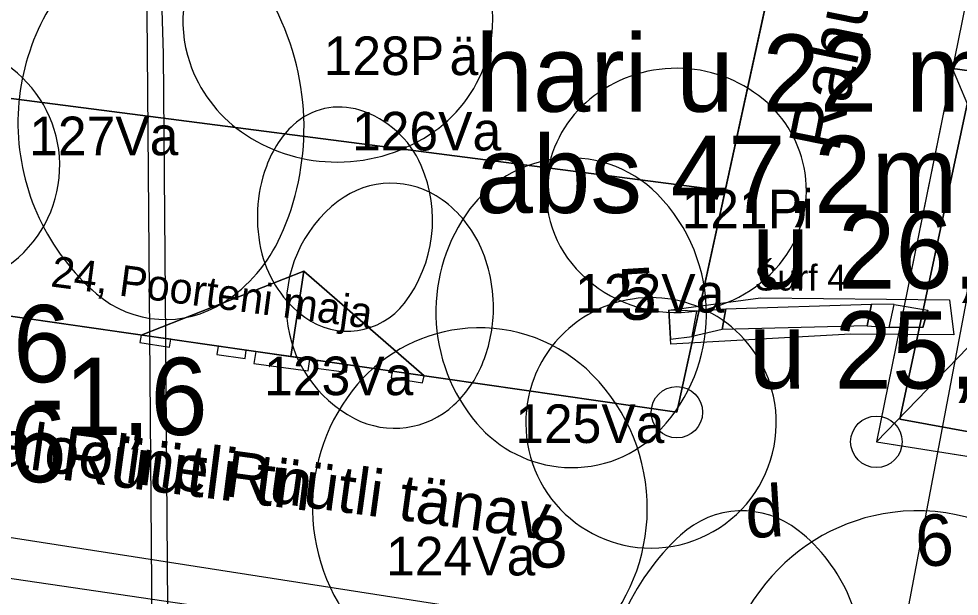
# Model space of a CAD drawing. Extents: x 738423 to 738903, y 6589762 to 6590172.
# Drawn here: x 738661.32 to 738697.88, y 6589853.54 to 6589875.99 of the extents above; entities that cross this region are included whole.
import ezdxf

# ---------------------------------------------------------------- set-up
doc = ezdxf.new("R2010")
doc.units = 0
for name, color, linetype in [('_1927_hoonestus', 7, 'Continuous'), ('_1927_katuse_kalded', 7, 'Continuous'), ('_1927_koordin_punktid_nr', 7, 'Continuous'), ('_1927_krundi_piir', 7, 'Continuous'), ('_a_ajalooline_maapind', 7, 'Continuous'), ('_a_olol_maapind', 7, 'Continuous'), ('_ajalooline_aadress', 7, 'Continuous'), ('_arheol_Raamatukogu_tekst', 7, 'Continuous'), ('_arheol_Suur10c_kõnnitee_plaadid', 7, 'Continuous'), ('_arheol_Suur10c_müür', 7, 'Continuous'), ('_arheol_Suur10c_sõidutee', 7, 'Continuous'), ('_arheol_Suur10c_tranžee', 7, 'Continuous'), ('a_dendro_II_Vkl_puu', 7, 'Continuous'), ('a_dendro_III_vk_puu', 7, 'Continuous'), ('a_dendro_puu_nr', 7, 'Continuous'), ('Default', 7, 'Continuous'), ('plan_ala', 7, 'Continuous'), ('v_olol_kitsendus_tehnov', 7, 'Continuous'), ('v_olol_kivimuur', 7, 'Continuous'), ('v_vormistus_tekst', 7, 'Continuous')]:
    doc.layers.add(name, color=color, linetype=linetype)

# ---------------------------------------------------------------- blocks, each defined once
blk = doc.blocks.new('_U564')
at = {"layer": 'Default'}
for centre, radius, start, end in [((0.00025099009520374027, -0.005055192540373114), 0.019094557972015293, 94.1124972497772, 134.51702665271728), ((0.0002459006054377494, -0.004984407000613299), 0.019023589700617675, 55.35000678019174, 94.11249724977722), ((0.002413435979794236, -0.0018482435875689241), 0.015211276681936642, 11.781229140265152, 55.3500067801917), ((-0.002483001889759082, -0.002274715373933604), 0.015195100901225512, 134.51702665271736, 180.0676771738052), ((0.0028111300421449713, -0.001765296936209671), 0.014805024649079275, 320.3120464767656, 11.781229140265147), ((-0.0028404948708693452, -0.002275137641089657), 0.014837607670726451, 180.06767717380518, 230.5602074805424), ((-0.00028961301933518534, 0.0008078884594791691), 0.018834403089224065, 275.0288867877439, 320.31204647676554), ((-0.0002910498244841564, 0.0008242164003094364), 0.01885079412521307, 230.56020748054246, 275.0288867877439)]:
    blk.add_arc(centre, radius, start, end, dxfattribs=at)
blk = doc.blocks.new('_U565')
at = {"layer": 'Default'}
for centre, radius, start, end in [((6.291324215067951e-05, -0.0048100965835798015), 0.02003728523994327, 93.63802698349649, 141.620131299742), ((1.0755175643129e-05, -0.003989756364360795), 0.019215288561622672, 47.2373133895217, 93.63802698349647), ((0.008279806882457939, 0.0049516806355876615), 0.007036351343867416, 326.00160298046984, 47.23731338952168), ((-0.010029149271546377, 0.003183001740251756), 0.0071633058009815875, 141.620131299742, 227.31101855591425), ((0.0031639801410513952, 0.008402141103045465), 0.013207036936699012, 297.16095567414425, 326.0016029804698), ((-0.005414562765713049, 0.00818571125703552), 0.01396929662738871, 227.31101855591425, 255.72135989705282), ((-0.0024036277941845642, 0.01925371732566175), 0.025403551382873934, 276.47252031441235, 297.16095567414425), ((-0.0024634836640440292, 0.019781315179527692), 0.025934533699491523, 255.72135989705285, 276.47252031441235)]:
    blk.add_arc(centre, radius, start, end, dxfattribs=at)
blk = doc.blocks.new('_U571')
at = {"layer": 'Default'}
for centre, radius, start, end in [((-0.001470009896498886, 0.001014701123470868), 0.00901042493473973, 85.84989655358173, 139.9854481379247), ((-0.0014878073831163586, 0.0007694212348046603), 0.009256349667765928, 43.48308981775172, 85.84989655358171), ((-0.000269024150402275, 6.4345285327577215e-06), 0.01057853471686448, 139.98544813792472, 189.65024392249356), ((-0.002518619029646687, -0.00020820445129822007), 0.0106770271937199, 4.160899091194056, 43.48308981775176), ((-0.0024551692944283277, -0.00020358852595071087), 0.01061340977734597, 325.0458822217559, 4.160899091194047), ((-0.00037917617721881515, -1.2295665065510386e-05), 0.01046680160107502, 189.65024392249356, 234.37896630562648), ((-0.0012850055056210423, -0.0010215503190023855), 0.009185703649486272, 282.866559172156, 325.0458822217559), ((-0.0012408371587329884, -0.0012149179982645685), 0.00898735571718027, 234.37896630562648, 282.866559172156)]:
    blk.add_arc(centre, radius, start, end, dxfattribs=at)
blk = doc.blocks.new('_U572')
at = {"layer": 'Default'}
for centre, radius, start, end in [((0.0006055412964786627, -0.0042978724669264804), 0.013370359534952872, 95.78793518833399, 134.72163124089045), ((0.0006103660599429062, -0.0043454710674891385), 0.013418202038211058, 57.679315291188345, 95.78793518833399), ((0.0025199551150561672, -0.0013272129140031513), 0.009846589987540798, 12.875543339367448, 57.67931529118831), ((-0.0019332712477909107, -0.0017342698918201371), 0.009762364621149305, 134.72163124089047, 180.63224075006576), ((0.0028947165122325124, -0.0012415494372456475), 0.009462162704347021, 318.8770820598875, 12.87554333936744), ((-0.002241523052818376, -0.0017376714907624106), 0.009454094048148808, 180.63224075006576, 231.2174139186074), ((4.354030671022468e-05, 0.0012476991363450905), 0.013247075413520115, 273.7532980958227, 318.87708205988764), ((5.212560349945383e-05, 0.001116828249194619), 0.013115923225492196, 231.21741391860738, 273.7532980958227)]:
    blk.add_arc(centre, radius, start, end, dxfattribs=at)
blk = doc.blocks.new('_U573')
at = {"layer": 'Default'}
for centre, radius, start, end in [((0.0006832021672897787, 0.002328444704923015), 0.009807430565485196, 99.69352009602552, 156.90409293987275), ((0.0007565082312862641, 0.0018992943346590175), 0.010242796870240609, 41.6418055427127, 99.69352009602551), ((0.0033334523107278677, 0.00419057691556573), 0.006794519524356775, 328.51143624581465, 41.6418055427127), ((-0.002092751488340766, 0.0035122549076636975), 0.006789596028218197, 156.90409293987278, 227.1622359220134), ((0.0013890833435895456, 0.005381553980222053), 0.009074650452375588, 297.72957352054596, 328.51143624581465), ((-0.0006159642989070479, 0.005104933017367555), 0.00896158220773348, 227.16223592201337, 250.19895822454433), ((0.00016828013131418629, 0.007703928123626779), 0.01169834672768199, 270.6931788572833, 297.72957352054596), ((0.0001732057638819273, 0.007296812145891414), 0.011291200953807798, 250.19895822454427, 270.6931788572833)]:
    blk.add_arc(centre, radius, start, end, dxfattribs=at)
blk = doc.blocks.new('_U574')
at = {"layer": 'Default'}
for centre, radius, start, end in [((-0.0019608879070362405, -0.0016410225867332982), 0.009734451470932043, 82.36591619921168, 131.76985429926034), ((-0.0019610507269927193, -0.0016422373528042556), 0.009735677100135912, 47.60610430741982, 82.36591619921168), ((-0.0019574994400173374, -0.0016448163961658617), 0.009739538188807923, 131.76985429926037, 181.1600261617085), ((-0.001964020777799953, -0.0016454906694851), 0.009740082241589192, 12.854403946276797, 47.60610430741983), ((-0.001964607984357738, -0.0016456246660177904), 0.009740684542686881, 329.7776812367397, 12.854403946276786), ((-0.001956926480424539, -0.0016448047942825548), 0.009740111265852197, 181.1600261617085, 233.9170109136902), ((-0.001960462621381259, -0.0016480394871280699), 0.009735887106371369, 286.68981658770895, 329.7776812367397), ((-0.0019601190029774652, -0.0016491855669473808), 0.009734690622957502, 233.91701091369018, 286.68981658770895)]:
    blk.add_arc(centre, radius, start, end, dxfattribs=at)
blk = doc.blocks.new('_U575')
at = {"layer": 'Default'}
for centre, radius, start, end in [((0.00042731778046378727, -0.002692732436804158), 0.01475472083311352, 95.42702457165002, 137.71551286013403), ((0.0004293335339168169, -0.002713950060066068), 0.01477603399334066, 53.94693546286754, 95.42702457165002), ((0.0017917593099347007, -0.0008423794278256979), 0.012461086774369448, 8.58220218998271, 53.946935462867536), ((-0.0012999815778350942, -0.0011218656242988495), 0.012419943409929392, 137.71551286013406, 184.01840102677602), ((0.0019030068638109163, -0.0008255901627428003), 0.012348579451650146, 318.9383698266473, 8.58220218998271), ((-0.0013715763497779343, -0.001126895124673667), 0.012348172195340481, 184.01840102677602, 230.9331406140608), ((9.492108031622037e-05, 0.0007495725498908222), 0.014746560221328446, 273.7559687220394, 318.9383698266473), ((9.916099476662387e-05, 0.0006849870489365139), 0.014681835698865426, 230.93314061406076, 273.7559687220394)]:
    blk.add_arc(centre, radius, start, end, dxfattribs=at)
blk = doc.blocks.new('_U578')
at = {"layer": 'Default'}
for centre, radius, start, end in [((0.0031046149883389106, 0.0007126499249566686), 0.010083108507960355, 58.964104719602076, 112.89361314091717), ((0.003381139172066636, 5.782187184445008e-05), 0.010793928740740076, 112.89361314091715, 149.17299112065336), ((0.0018851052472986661, -0.001314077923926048), 0.01244844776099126, 10.793615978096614, 58.964104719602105), ((0.005224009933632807, -0.001041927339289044), 0.012939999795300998, 149.1729911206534, 182.21275775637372), ((0.0016087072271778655, -0.0013667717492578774), 0.012729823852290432, 316.8121326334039, 10.793615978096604), ((0.005405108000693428, -0.0010349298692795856), 0.013121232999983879, 182.2127577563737, 217.26007191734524), ((0.0036931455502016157, -0.0023372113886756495), 0.010970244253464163, 217.26007191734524, 255.71243530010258), ((0.0034904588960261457, -0.0031331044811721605), 0.010148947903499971, 255.71243530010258, 316.8121326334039)]:
    blk.add_arc(centre, radius, start, end, dxfattribs=at)
blk = doc.blocks.new('_U576')
at = {"layer": 'Default'}
for centre, radius, start, end in [((-0.003355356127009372, -0.008989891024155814), 0.011452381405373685, 74.0956447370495, 108.61486101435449), ((-0.004187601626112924, -0.006519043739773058), 0.008845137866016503, 108.61486101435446, 148.07755350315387), ((-0.0027526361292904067, -0.006874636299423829), 0.009252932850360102, 61.394012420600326, 74.09564473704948), ((-0.001780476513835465, -0.005092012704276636), 0.007222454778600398, 47.00906118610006, 61.394012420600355), ((-0.00046350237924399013, -0.0036792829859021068), 0.005291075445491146, 346.8046159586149, 47.00906118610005), ((-0.0069482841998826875, -0.004799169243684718), 0.005592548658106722, 148.0775535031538, 236.8517004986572), ((-0.0028699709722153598, -0.0031150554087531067), 0.007762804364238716, 297.88330635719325, 346.80461595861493), ((-0.004202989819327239, -0.0005956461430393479), 0.010613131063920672, 236.85170049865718, 297.88330635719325)]:
    blk.add_arc(centre, radius, start, end, dxfattribs=at)
blk = doc.blocks.new('_U577')
at = {"layer": 'Default'}
for centre, radius, start, end in [((0.0003539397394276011, -0.0024772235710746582), 0.01753301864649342, 95.06339460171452, 143.64928581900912), ((0.0003509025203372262, -0.0024429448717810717), 0.017498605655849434, 47.6139328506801, 95.06339460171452), ((0.006587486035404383, 0.004390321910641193), 0.008247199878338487, 335.85757945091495, 47.613932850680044), ((-0.007106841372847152, 0.0030134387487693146), 0.008269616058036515, 143.6492858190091, 217.25092224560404), ((0.00326511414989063, 0.0058794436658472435), 0.011888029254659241, 301.16151048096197, 335.85757945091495), ((-0.004085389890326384, 0.00531108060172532), 0.012065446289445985, 217.2509222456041, 249.96613917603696), ((-0.0012283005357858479, 0.013310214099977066), 0.02057175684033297, 274.9595126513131, 301.16151048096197), ((-0.0012168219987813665, 0.01317793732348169), 0.020438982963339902, 249.96613917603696, 274.9595126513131)]:
    blk.add_arc(centre, radius, start, end, dxfattribs=at)
blk = doc.blocks.new('_U579')
at = {"layer": 'Default'}
for centre, radius, start, end in [((-0.00040469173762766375, -0.0036338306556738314), 0.00964728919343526, 90.6698769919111, 129.9961164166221), ((-0.00040544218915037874, -0.003569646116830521), 0.009583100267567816, 57.797497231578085, 90.6698769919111), ((-8.07417360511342e-05, -0.003054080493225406), 0.008973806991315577, 23.79468007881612, 57.797497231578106), ((-0.0008287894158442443, -0.0031283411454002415), 0.00898745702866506, 129.99611641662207, 170.80227761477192), ((0.00012402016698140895, -0.00296379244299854), 0.008750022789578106, 330.06495980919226, 23.79468007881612), ((-0.0010439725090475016, -0.0030934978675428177), 0.008769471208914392, 170.80227761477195, 225.9110289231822), ((-0.000504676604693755, -0.002601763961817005), 0.009475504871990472, 278.59055247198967, 330.06495980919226), ((-0.0005131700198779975, -0.002545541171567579), 0.009532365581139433, 225.91102892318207, 278.59055247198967)]:
    blk.add_arc(centre, radius, start, end, dxfattribs=at)

msp = doc.modelspace()

# ---------------------------------------------------------------- linework, layer by layer
at = {"layer": '_1927_hoonestus'}
for points in [[(738686.9079452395, 6589860.693508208), (738690.3471033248, 6589876.437885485), (738655.8073303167, 6589881.431195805), (738653.971798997, 6589865.440014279)], [(738697.6203724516, 6589874.0571487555), (738694.6643747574, 6589859.543029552), (738701.5400623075, 6589858.454941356), (738701.6672655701, 6589859.306230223), (738695.5732603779, 6589860.420766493), (738698.2877155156, 6589873.09433022), (738708.37858821, 6589871.7342214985), (738707.9133168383, 6589868.775731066), (738709.1198007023, 6589868.597835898), (738709.3011963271, 6589869.828059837), (738709.6806366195, 6589872.401421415)], [(738698.2877155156, 6589873.09433022), (738695.5732603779, 6589860.420766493), (738701.6672655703, 6589859.306230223), (738703.186385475, 6589869.472713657), (738707.9133168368, 6589868.775731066), (738708.37858821, 6589871.7342214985)], [(738666.0829986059, 6589863.6946406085), (738666.0226137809, 6589863.40871552), (738667.1852757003, 6589863.227095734), (738667.2336050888, 6589863.528823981)], [(738669.0718007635, 6589863.263917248), (738669.0201426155, 6589862.940511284), (738670.1198644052, 6589862.787255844), (738670.1682470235, 6589863.105905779)], [(738670.5345586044, 6589863.053115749), (738670.4615629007, 6589862.583018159), (738672.5748457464, 6589862.303206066), (738672.6434326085, 6589862.74920092)], [(738672.9281124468, 6589862.708175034), (738672.8870732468, 6589862.4073190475), (738674.0567893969, 6589862.247760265), (738674.0969044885, 6589862.539737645)], [(738675.8365255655, 6589862.289036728), (738675.7958205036, 6589862.024044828), (738677.0225699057, 6589861.835605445), (738677.0811269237, 6589862.109674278)]]:
    msp.add_lwpolyline(points, close=True, dxfattribs=at)
at = {"layer": '_1927_katuse_kalded'}
for points in [[(738654.1081769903, 6589873.783129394), (738655.0056644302, 6589881.575610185), (738655.8073303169, 6589881.431195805), (738690.3471033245, 6589876.437885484), (738688.7887442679, 6589869.303757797)], [(738694.6643747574, 6589859.543029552), (738701.0004892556, 6589866.068740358), (738697.6203724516, 6589874.0571487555)], [(738702.6437962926, 6589865.841516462), (738701.0004892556, 6589866.068740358), (738697.6203724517, 6589874.0571487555), (738709.6806366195, 6589872.401421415), (738709.1215019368, 6589868.609373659), (738707.9133168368, 6589868.775731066), (738703.1863854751, 6589869.472713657)], [(738654.1081769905, 6589873.783129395), (738688.788744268, 6589869.303757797), (738686.9079452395, 6589860.693508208), (738677.0811269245, 6589862.109674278), (738672.4076793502, 6589866.177638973), (738666.0829986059, 6589863.694640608), (738653.1607330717, 6589865.55689891)], [(738672.4076793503, 6589866.177638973), (738671.9013747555, 6589862.856140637), (738666.0829986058, 6589863.6946406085)], [(738672.4076793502, 6589866.177638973), (738677.0811269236, 6589862.109674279), (738671.9013747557, 6589862.856140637)], [(738694.6643747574, 6589859.543029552), (738701.5400623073, 6589858.454941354), (738702.6437962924, 6589865.841516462), (738701.0004892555, 6589866.0687403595)]]:
    msp.add_lwpolyline(points, close=True, dxfattribs=at)
at = {"layer": '_1927_koordin_punktid_nr'}
for centre in [(738686.9079452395, 6589860.693508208), (738694.6643747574, 6589859.543029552)]:
    msp.add_circle(centre, 0.9999999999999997, dxfattribs=at)
at = {"layer": '_1927_krundi_piir'}
for points in [[(738699.2597677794, 6589917.23983417), (738686.9079452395, 6589860.693508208), (738653.160733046, 6589865.556898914), (738635.0048101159, 6589867.503013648), (738638.1290908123, 6589898.927727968), (738639.279366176, 6589910.5516114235)], [(738701.0341576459, 6589890.819030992), (738694.6643747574, 6589859.543029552), (738727.0653921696, 6589854.415518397)]]:
    msp.add_lwpolyline(points, dxfattribs=at)
msp.add_lwpolyline([(738633.9361268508, 6589860.04223513), (738644.9741249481, 6589858.324475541), (738684.978134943, 6589852.097053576), (738681.439240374, 6589832.970330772), (738673.9180075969, 6589806.512115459), (738663.8382523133, 6589773.993292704), (738643.3161389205, 6589777.57560507), (738622.7595626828, 6589780.584670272), (738626.6204084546, 6589806.9353357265), (738627.9771447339, 6589816.20750196), (738629.4457483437, 6589826.258119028), (738630.9080977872, 6589836.248230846)], close=True, dxfattribs=at)
at = {"layer": '_arheol_Suur10c_kõnnitee_plaadid'}
for p, q in [((738688.6749999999, 6589863.909), (738688.8119999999, 6589864.717999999)), ((738694.303, 6589864.046), (738694.476, 6589864.898))]:
    msp.add_line(p, q, dxfattribs=at)
for points in [[(738688.8119999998, 6589864.718000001), (738688.6749999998, 6589863.909000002), (738687.5074551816, 6589863.6329958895), (738687.687, 6589864.623)], [(738695.358, 6589864.879000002), (738694.4760000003, 6589864.897999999), (738694.3030000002, 6589864.045999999), (738695.156, 6589863.990000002)]]:
    msp.add_lwpolyline(points, close=True, dxfattribs=at)
at = {"layer": '_arheol_Suur10c_müür'}
for p, q in [((738695.156, 6589863.989999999), (738695.358, 6589864.879)), ((738687.5079999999, 6589863.636), (738687.6869999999, 6589864.623)), ((738696.476, 6589863.988), (738696.661, 6589864.66))]:
    msp.add_line(p, q, dxfattribs=at)
for points in [[(738695.358, 6589864.879000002), (738696.661, 6589864.660000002), (738696.476, 6589863.988000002), (738695.156, 6589863.990000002)], [(738687.687, 6589864.623), (738686.59, 6589864.663999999), (738686.6593704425, 6589863.538845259), (738687.5074551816, 6589863.632995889)]]:
    msp.add_lwpolyline(points, close=True, dxfattribs=at)
at = {"layer": '_arheol_Suur10c_sõidutee'}
msp.add_lwpolyline([(738688.8119999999, 6589864.717999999), (738694.476, 6589864.898), (738694.303, 6589864.046), (738688.6749999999, 6589863.909)], close=True, dxfattribs=at)
at = {"layer": '_arheol_Suur10c_tranžee'}
msp.add_lwpolyline([(738686.672, 6589863.334), (738686.59, 6589864.664), (738690.1549999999, 6589865.146), (738697.5079999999, 6589865.057999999), (738697.672, 6589863.699), (738693.6599999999, 6589863.721)], close=True, dxfattribs=at)
at = {"layer": 'plan_ala'}
msp.add_lwpolyline([(738772.2221966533, 6589837.873120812), (738583.11, 6589865.669999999), (738583.11, 6589865.669999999), (738577.13, 6589865.85), (738565.7035831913, 6589866.139410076), (738565.4500000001, 6589885.77), (738564.4932191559, 6589941.052825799), (738581.9, 6589941.1499999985), (738615.11, 6589942.169999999), (738650.0499999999, 6589943.319999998), (738691.2690631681, 6589944.800325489), (738696.0901513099, 6589944.851371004), (738713.89, 6589945.129999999), (738703.51, 6589987.789999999), (738752.8799999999, 6590000.39), (738783.1408503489, 6590007.463828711), (738767.5688789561, 6589951.87996157)], close=True, dxfattribs=at)
at = {"layer": 'v_olol_kitsendus_tehnov'}
msp.add_line((738695.1721002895, 6589849.198420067), (738701.4019006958, 6589882.123978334), dxfattribs=at)
at = {"layer": 'v_olol_kivimuur'}
msp.add_lwpolyline([(738670.507, 6589877.989), (738669.2659999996, 6589877.994000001), (738669.256, 6589877.913000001), (738666.5159999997, 6589877.836), (738666.2819999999, 6589877.638000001), (738666.319, 6589874.704), (738666.3879999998, 6589865.342000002), (738666.6002612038, 6589839.331603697), (738667.2190409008, 6589839.230293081), (738667.0289999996, 6589865.218000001), (738666.944, 6589874.627999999), (738666.871, 6589877.199999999), (738670.5099999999, 6589877.303999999)], close=True, dxfattribs=at)

# ---------------------------------------------------------------- block references
at = {"layer": 'a_dendro_II_Vkl_puu', "xscale": 500.0000000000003, "yscale": 500.0000000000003, "rotation": 85.69234851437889}
for name, p in [('_U578', (738672.9843105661, 6589874.321442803)), ('_U577', (738668.8083105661, 6589871.8624428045)), ('_U572', (738682.0553105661, 6589864.449442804)), ('_U574', (738685.157310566, 6589861.318442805)), ('_U575', (738678.756, 6589856.883999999)), ('_U564', (738695.2643105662, 6589848.125442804)), ('_U565', (738691.605310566, 6589849.025442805))]:
    msp.add_blockref(name, p, dxfattribs=at)
at = {"layer": 'a_dendro_III_vk_puu', "xscale": 500.0000000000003, "yscale": 500.0000000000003, "rotation": 85.69234851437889}
for name, p in [('_U579', (738656.897310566, 6589870.628442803)), ('_U571', (738686.8903105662, 6589869.990442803)), ('_U576', (738671.9663105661, 6589870.282442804)), ('_U573', (738677.762310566, 6589864.376442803))]:
    msp.add_blockref(name, p, dxfattribs=at)

# ---------------------------------------------------------------- texts
at = {"layer": '_1927_koordin_punktid_nr'}
for s, height, rotation, p in [('Rahu tn', 1.999999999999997, 78.4840469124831, (738693.2020124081, 6589870.754290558)), ('5', 1.9999999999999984, 3.560863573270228, (738684.6807148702, 6589864.243998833)), ('Rüütli tn', 1.9999999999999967, 352.76354685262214, (738662.8885350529, 6589858.085805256)), ('d', 1.9999999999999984, 3.560863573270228, (738689.625529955, 6589855.789466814)), ('8', 1.9999999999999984, 3.560863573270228, (738681.2101480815, 6589854.610269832)), ('6', 1.9999999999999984, 3.560863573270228, (738696.2376669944, 6589854.675728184))]:
    msp.add_text(s, height=height, rotation=rotation, dxfattribs=at).set_placement(p)
at = {"layer": '_a_ajalooline_maapind'}
for s, p in [('u 25,5', (738689.6931667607, 6589861.614688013)), ('-1,6', (738661.7549853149, 6589859.808941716)), ('25,86', (738653.1542820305, 6589857.973600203))]:
    msp.add_text(s, height=3, dxfattribs=at).set_placement(p)
at = {"layer": '_a_olol_maapind'}
for s, p in [('hari u 22 m', (738679.0830971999, 6589872.376304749)), ('abs 47,2m', (738679.0830971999, 6589868.439831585)), ('u 26,2 m', (738689.8277116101, 6589865.501311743)), ('27,46', (738653.2888268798, 6589861.860223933))]:
    msp.add_text(s, height=3, dxfattribs=at).set_placement(p)
at = {"layer": '_ajalooline_aadress'}
msp.add_text('24, Poorteni maja', height=1.2, rotation=352.4627473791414, dxfattribs=at).set_placement((738662.527072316, 6589865.586646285))
at = {"layer": '_arheol_Raamatukogu_tekst'}
msp.add_text('Šurf 4', height=1.0000000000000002, rotation=359.99285992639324, dxfattribs=at).set_placement((738689.9295376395, 6589865.42436747))
at = {"layer": 'a_dendro_puu_nr'}
for s, p in [('128P', (738673.1748701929, 6589873.799425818)), ('ä', (738678.06879928, 6589873.799425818)), ('126Va', (738674.2776910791, 6589870.869648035)), ('127Va', (738661.727102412, 6589870.684831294)), ('121Pi', (738687.091971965, 6589867.843549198)), ('122Va', (738682.9532551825, 6589864.566354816)), ('123Va', (738670.8625330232, 6589861.3559864)), ('125Va', (738680.6244969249, 6589859.496860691)), ('124Va', (738675.6052152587, 6589854.348823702))]:
    msp.add_text(s, height=1.5, dxfattribs=at).set_placement(p)
at = {"layer": 'v_vormistus_tekst'}
msp.add_text('ajalooline Rüütli tänav', height=1.7999999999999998, rotation=352.22707759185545, dxfattribs=at).set_placement((738658.5210745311, 6589858.907780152))

doc.saveas('drawing.dxf')
